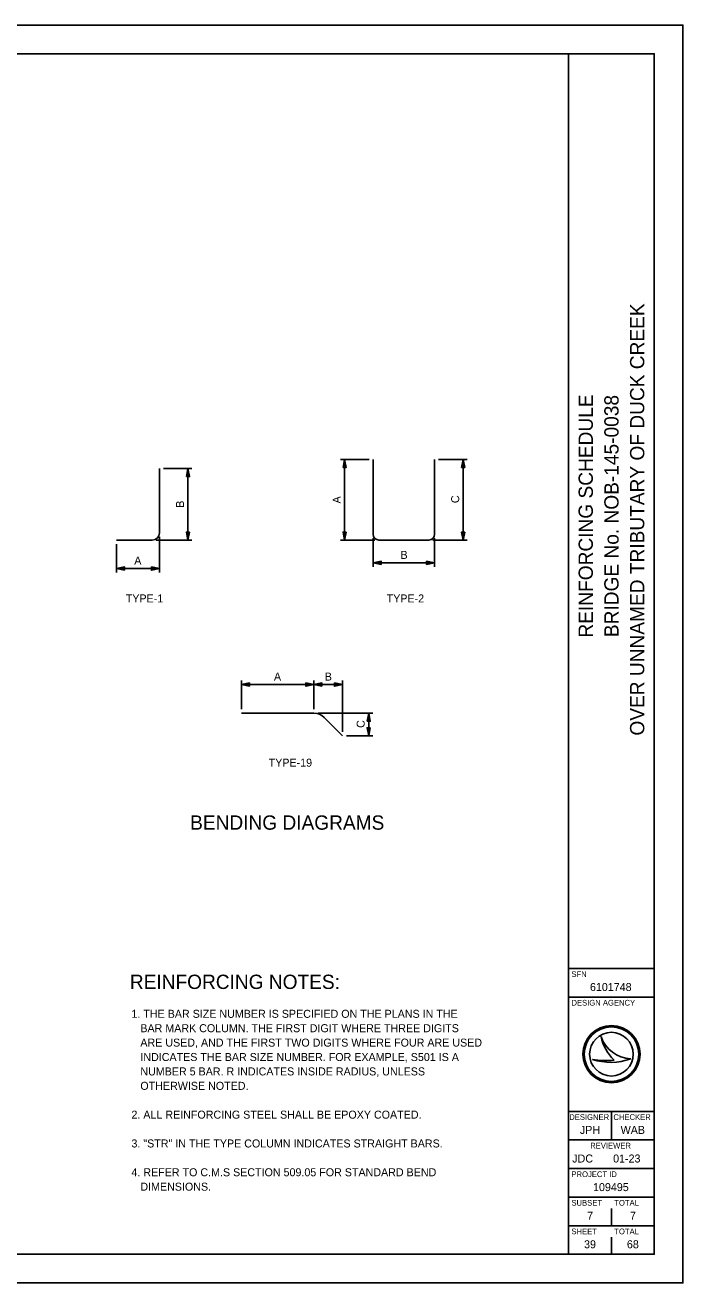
# Model space of a CAD drawing. Extents: x -375 to 456, y -77 to 177.
# Drawn here: x 189.6 to 224.2, y -61 to 5 of the extents above; entities that cross this region are included whole.
import ezdxf

# ---------------------------------------------------------------- set-up
doc = ezdxf.new("R2010")
doc.units = 0
for name, color, linetype in [('BR_P_Gen_NonPerf_Pipe', 7, 'Continuous'), ('BR_P_Gen_Text', 7, 'Continuous'), ('SH_Border', 7, 'Continuous'), ('SH_Cut_Line', 7, 'Continuous'), ('SH_Data', 7, 'Continuous'), ('TX_P_10', 7, 'Continuous')]:
    doc.layers.add(name, color=color, linetype=linetype)

msp = doc.modelspace()

# ---------------------------------------------------------------- linework, layer by layer
at = {"layer": 'BR_P_Gen_Text'}
for p, q in [((207.682, -17.751), (206.183, -17.751)), ((206.393, -17.751), (206.393, -21.983)), ((207.892, -17.751), (207.892, -21.683)), ((211.117, -21.683), (211.117, -17.751)), ((211.327, -17.751), (212.827, -17.751)), ((212.617, -17.751), (212.617, -21.983)), ((196.668, -21.608), (196.668, -18.233)), ((196.878, -18.233), (198.377, -18.233)), ((198.168, -18.233), (198.168, -21.983)), ((194.418, -21.983), (196.293, -21.983)), ((194.418, -22.193), (194.418, -23.692)), ((196.503, -21.983), (198.377, -21.983)), ((196.668, -21.818), (196.668, -23.692)), ((207.982, -21.983), (206.183, -21.983)), ((207.892, -21.893), (207.892, -23.392)), ((208.192, -21.983), (210.817, -21.983)), ((211.027, -21.983), (212.827, -21.983)), ((211.117, -21.893), (211.117, -23.392)), ((194.418, -23.482), (196.668, -23.482)), ((207.892, -23.182), (211.117, -23.182)), ((200.97, -30.859), (200.97, -29.359)), ((204.784, -29.569), (200.97, -29.569)), ((204.784, -30.859), (204.784, -29.359)), ((204.784, -30.859), (204.784, -29.359)), ((204.784, -29.569), (206.277, -29.569)), ((206.277, -32.041), (206.277, -29.359)), ((204.784, -31.069), (200.97, -31.069)), ((204.994, -31.069), (207.865, -31.069)), ((205.314, -31.289), (206.277, -32.251)), ((207.655, -32.251), (207.655, -31.069)), ((206.487, -32.251), (207.865, -32.251))]:
    msp.add_line(p, q, dxfattribs=at)
for points in [[(206.309, -18.171), (206.393, -17.751), (206.477, -18.171)], [(212.533, -18.171), (212.617, -17.751), (212.701, -18.171)], [(198.084, -18.653), (198.168, -18.233), (198.252, -18.653)], [(198.252, -21.563), (198.168, -21.983), (198.084, -21.563)], [(206.477, -21.563), (206.393, -21.983), (206.309, -21.563)], [(212.701, -21.563), (212.617, -21.983), (212.533, -21.563)], [(208.312, -23.266), (207.892, -23.182), (208.312, -23.098)], [(210.697, -23.098), (211.117, -23.182), (210.697, -23.266)], [(194.838, -23.566), (194.418, -23.482), (194.838, -23.398)], [(196.248, -23.398), (196.668, -23.482), (196.248, -23.566)], [(201.39, -29.653), (200.97, -29.569), (201.39, -29.485)], [(204.364, -29.485), (204.784, -29.569), (204.364, -29.653)], [(205.204, -29.653), (204.784, -29.569), (205.204, -29.485)], [(205.857, -29.485), (206.277, -29.569), (205.857, -29.653)], [(207.571, -31.489), (207.655, -31.069), (207.739, -31.489)], [(207.739, -31.831), (207.655, -32.251), (207.571, -31.831)]]:
    msp.add_lwpolyline(points, close=True, dxfattribs=at)
for centre, radius, start, end in [((196.293, -21.608), 0.375, 270, 360), ((208.192, -21.683), 0.3, 180, 270), ((210.817, -21.683), 0.3, 270, 360), ((204.784, -31.819), 0.75, 45, 90)]:
    msp.add_arc(centre, radius, start, end, dxfattribs=at)
at = {"layer": 'SH_Border'}
for p, q in [((218.153, -59.464), (218.153, 3.536)), ((218.153, -44.464), (222.653, -44.464)), ((218.153, -45.964), (222.653, -45.964)), ((218.153, -51.964), (222.653, -51.964)), ((220.403, -51.964), (220.403, -53.464)), ((218.153, -53.464), (222.653, -53.464)), ((218.153, -54.964), (222.653, -54.964)), ((218.153, -56.464), (222.653, -56.464)), ((218.153, -57.964), (222.653, -57.964))]:
    msp.add_line(p, q, dxfattribs=at)
msp.add_lwpolyline([(126.653, 3.536), (222.653, 3.536), (222.653, -59.464), (126.653, -59.464)], close=True, dxfattribs=at)
at = {"layer": 'SH_Cut_Line'}
msp.add_lwpolyline([(122.153, -60.964), (224.153, -60.964), (224.153, 5.036), (122.153, 5.036)], close=True, dxfattribs=at)
at = {"layer": 'SH_Data'}
for p, q in [((219.855, -48.035), (219.855, -48.035)), ((219.404, -49.235), (219.404, -49.235)), ((220.403, -48.964), (220.403, -48.964)), ((221.415, -49.208), (221.415, -49.208)), ((220.403, -57.964), (220.403, -57.064)), ((220.403, -59.464), (220.403, -58.564)), ((219.278, -58.939), (219.278, -58.939))]:
    msp.add_line(p, q, dxfattribs=at)
for radius in [1.5, 1.43, 1.43, 1.147]:
    msp.add_circle((220.403, -48.964), radius, dxfattribs=at)
for centre, radius, start, end in [((221.501, -47.471), 1.74, 198.92567, 198.93195), ((222.193, -47.554), 2.387, 191.63793, 191.64215), ((221.501, -47.471), 1.74, 198.93195, 267.16574), ((222.193, -47.554), 2.387, 191.64215, 226.09467), ((220.097, -45.501), 3.798, 259.49639, 259.49952), ((220.371, -46.354), 3.039, 251.45274, 251.45764), ((220.371, -46.354), 3.039, 251.45764, 290.08324), ((220.097, -45.501), 3.798, 259.49952, 276.66723)]:
    msp.add_arc(centre, radius, start, end, dxfattribs=at)

# ---------------------------------------------------------------- texts
at = {"layer": 'BR_P_Gen_NonPerf_Pipe'}
for s, p in [('1. THE BAR SIZE NUMBER IS SPECIFIED ON THE PLANS IN THE', (195.198, -47.055)), ('   BAR MARK COLUMN. THE FIRST DIGIT WHERE THREE DIGITS', (195.198, -47.811)), ('   ARE USED, AND THE FIRST TWO DIGITS WHERE FOUR ARE USED ', (195.198, -48.567)), ('   INDICATES THE BAR SIZE NUMBER. FOR EXAMPLE, S501 IS A ', (195.198, -49.323)), ('   NUMBER 5 BAR. R INDICATES INSIDE RADIUS, UNLESS', (195.198, -50.079)), ('   OTHERWISE NOTED.', (195.198, -50.835)), ('2. ALL REINFORCING STEEL SHALL BE EPOXY COATED.', (195.198, -52.347)), ('3. "STR" IN THE TYPE COLUMN INDICATES STRAIGHT BARS.', (195.198, -53.859)), ('4. REFER TO C.M.S SECTION 509.05 FOR STANDARD BEND ', (195.198, -55.371)), ('   DIMENSIONS.', (195.198, -56.127))]:
    msp.add_text(s, height=0.42, dxfattribs=at).set_placement(p)
at = {"layer": 'BR_P_Gen_Text'}
for s, p in [('A', (206.183, -20.063)), ('C', (212.407, -20.047)), ('B', (197.958, -20.288)), ('C', (207.445, -31.841))]:
    msp.add_text(s, height=0.42, rotation=90, dxfattribs=at).set_placement(p)
for s, p in [('A', (195.347, -23.272)), ('B', (209.325, -22.972)), ('A', (202.681, -29.359)), ('B', (205.35, -29.359))]:
    msp.add_text(s, height=0.42, dxfattribs=at).set_placement(p)
at = {"layer": 'SH_Data'}
for s, p in [('OVER UNNAMED TRIBUTARY OF DUCK CREEK', (222.128, -32.245)), ('REINFORCING SCHEDULE', (219.428, -27.103)), ('BRIDGE No. NOB-145-0038', (220.778, -27.079))]:
    msp.add_text(s, height=0.75, rotation=90, dxfattribs=at).set_placement(p)
for s, height, p in [('BENDING DIAGRAMS', 0.75, (198.28, -37.184)), ('REINFORCING NOTES:', 0.75, (195.115, -45.542)), ('SFN', 0.3, (218.303, -44.914)), ('6101748', 0.42, (219.274, -45.649)), ('DESIGN AGENCY', 0.3, (218.303, -46.414)), ('DESIGNER', 0.3, (218.186, -52.414)), ('CHECKER', 0.3, (220.506, -52.414)), ('JPH', 0.42, (218.747, -53.149)), ('WAB', 0.42, (220.886, -53.149)), ('REVIEWER', 0.3, (219.288, -53.914)), ('JDC', 0.42, (218.344, -54.649)), ('01-23', 0.42, (220.491, -54.649)), ('PROJECT ID', 0.3, (218.303, -55.414)), ('109495', 0.42, (219.436, -56.149)), ('SUBSET', 0.3, (218.303, -56.914)), ('TOTAL', 0.3, (220.553, -56.914)), ('7', 0.42, (219.128, -57.649)), ('7', 0.42, (221.378, -57.649)), ('SHEET', 0.3, (218.303, -58.414)), ('39', 0.42, (218.965, -59.149)), ('TOTAL', 0.3, (220.553, -58.414)), ('68', 0.42, (221.215, -59.149))]:
    msp.add_text(s, height=height, dxfattribs=at).set_placement(p)
at = {"layer": 'TX_P_10'}
for s, p in [('TYPE-1', (194.901, -25.258)), ('TYPE-2', (208.599, -25.258)), ('TYPE-19', (202.404, -33.877))]:
    msp.add_text(s, height=0.42, dxfattribs=at).set_placement(p)

doc.saveas('drawing.dxf')
